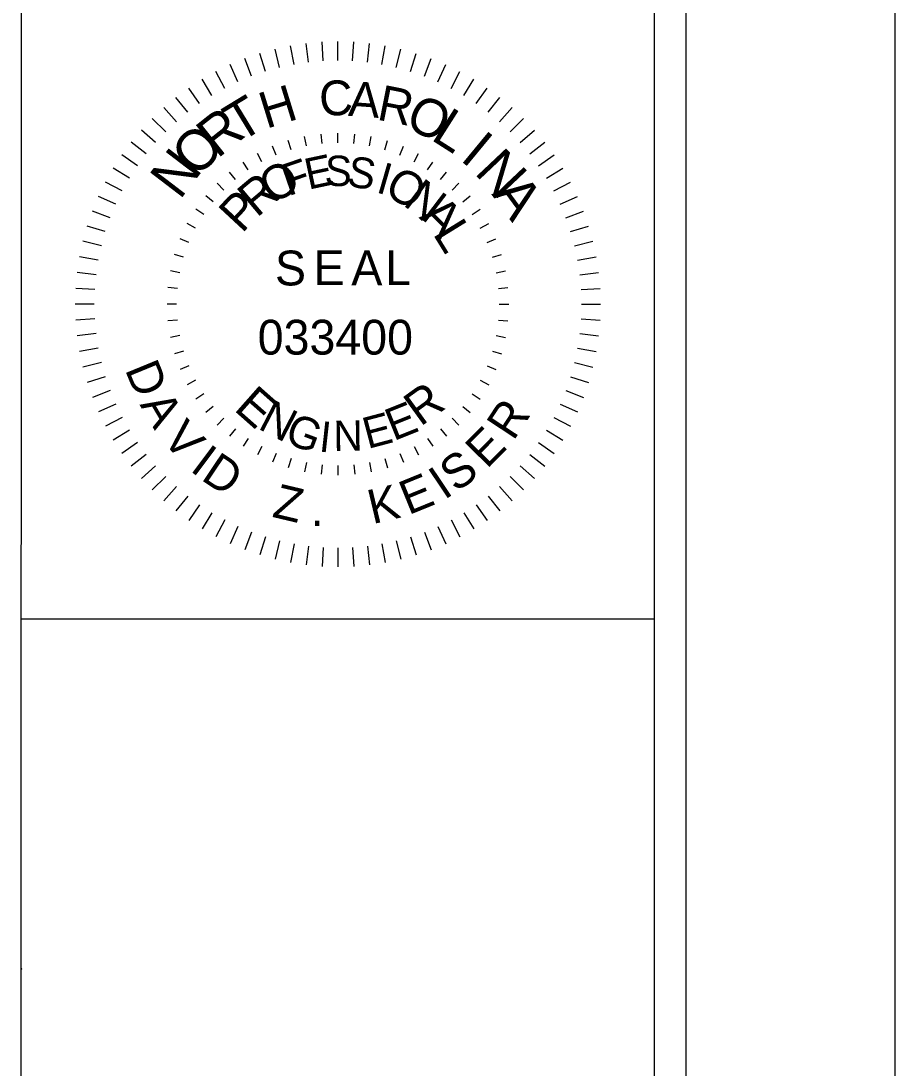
# Model space of a CAD drawing. Extents: x -2362 to 1945, y 0 to 1100.
# Drawn here: x 1561.9 to 1700, y 775.7 to 941 of the extents above; entities that cross this region are included whole.
import ezdxf

# ---------------------------------------------------------------- set-up
doc = ezdxf.new("R2010")
doc.units = 0
for name, color, linetype in [('Exist Utilities Telephone Test Hole SUE LOS A CELL', 7, 'Continuous'), ('Exist Utilities Water Test Hole SUE LOS A CELL', 7, 'Continuous'), ('Sheet PE Seal CELL', 7, 'Continuous'), ('Sheet_Symbology_CELL', 7, 'Continuous'), ('z - Construction', 7, 'Continuous')]:
    doc.layers.add(name, color=color, linetype=linetype)

msp = doc.modelspace()

# ---------------------------------------------------------------- linework, layer by layer
at = {"layer": 'Exist Utilities Telephone Test Hole SUE LOS A CELL'}
msp.add_line((1699.98, 0), (1699.98, 1100), dxfattribs=at)
at = {"layer": 'Exist Utilities Water Test Hole SUE LOS A CELL'}
msp.add_circle((1561.99, 791.38), 0.0603, dxfattribs=at)
at = {"layer": 'Sheet PE Seal CELL'}
msp.add_line((1661.97, 846.56), (1561.97, 846.56), dxfattribs=at)
at = {"layer": 'Sheet_Symbology_CELL'}
for p, q in [((1607.36, 934.51), (1607, 937.48)), ((1609.67, 934.72), (1609.49, 937.71)), ((1612, 934.79), (1612, 937.79)), ((1614.32, 934.72), (1614.5, 937.71)), ((1616.64, 934.51), (1617, 937.48)), ((1600.55, 933.04), (1599.66, 935.91)), ((1602.79, 933.67), (1602.07, 936.58)), ((1605.06, 934.16), (1604.52, 937.11)), ((1618.93, 934.16), (1619.48, 937.11)), ((1621.21, 933.67), (1621.92, 936.58)), ((1623.44, 933.04), (1624.34, 935.91)), ((1596.21, 931.4), (1594.98, 934.13)), ((1598.35, 932.29), (1597.29, 935.09)), ((1625.64, 932.29), (1626.71, 935.09)), ((1627.79, 931.4), (1629.02, 934.13)), ((1594.12, 930.38), (1592.72, 933.03)), ((1629.88, 930.38), (1631.27, 933.03)), ((1592.09, 929.24), (1590.54, 931.81)), ((1631.9, 929.24), (1633.45, 931.81)), ((1590.14, 927.98), (1588.44, 930.44)), ((1633.85, 927.98), (1635.56, 930.44)), ((1588.27, 926.6), (1586.42, 928.96)), ((1635.73, 926.6), (1637.58, 928.96)), ((1586.48, 925.11), (1584.49, 927.35)), ((1637.51, 925.11), (1639.5, 927.36)), ((1584.79, 923.52), (1582.67, 925.64)), ((1639.21, 923.52), (1641.32, 925.64)), ((1583.2, 921.82), (1580.95, 923.81)), ((1607.03, 921.31), (1606.73, 922.78)), ((1609.5, 921.67), (1609.35, 923.16)), ((1612, 921.8), (1612, 923.29)), ((1614.5, 921.67), (1614.64, 923.16)), ((1616.97, 921.31), (1617.26, 922.78)), ((1640.8, 921.82), (1643.04, 923.81)), ((1581.71, 920.04), (1579.35, 921.89)), ((1602.25, 919.85), (1601.67, 921.24)), ((1604.6, 920.7), (1604.16, 922.13)), ((1619.39, 920.7), (1619.83, 922.13)), ((1621.75, 919.85), (1622.33, 921.24)), ((1642.29, 920.04), (1644.65, 921.89)), ((1580.33, 918.17), (1577.87, 919.87)), ((1599.98, 918.79), (1599.28, 920.11)), ((1624.01, 918.79), (1624.72, 920.11)), ((1643.66, 918.17), (1646.13, 919.87)), ((1579.07, 916.22), (1576.5, 917.77)), ((1597.84, 917.5), (1597.01, 918.75)), ((1626.16, 917.5), (1626.99, 918.75)), ((1644.93, 916.22), (1647.49, 917.77)), ((1595.83, 916.01), (1594.88, 917.17)), ((1628.17, 916.01), (1629.12, 917.17)), ((1577.93, 914.19), (1575.27, 915.58)), ((1593.98, 914.33), (1592.92, 915.39)), ((1630.02, 914.33), (1631.08, 915.39)), ((1646.07, 914.19), (1648.72, 915.59)), ((1576.91, 912.1), (1574.18, 913.33)), ((1592.3, 912.48), (1591.14, 913.43)), ((1631.7, 912.48), (1632.86, 913.43)), ((1647.09, 912.1), (1649.82, 913.33)), ((1576.02, 909.95), (1573.22, 911.02)), ((1590.81, 910.47), (1589.56, 911.3)), ((1633.19, 910.47), (1634.44, 911.3)), ((1647.97, 909.95), (1650.78, 911.02)), ((1575.26, 907.76), (1572.4, 908.65)), ((1589.52, 908.32), (1588.2, 909.03)), ((1634.47, 908.32), (1635.8, 909.03)), ((1648.74, 907.76), (1651.59, 908.65)), ((1574.64, 905.52), (1571.73, 906.24)), ((1588.45, 906.06), (1587.07, 906.63)), ((1635.54, 906.06), (1636.93, 906.63)), ((1649.36, 905.52), (1652.27, 906.24)), ((1574.15, 903.25), (1571.2, 903.79)), ((1587.61, 903.71), (1586.17, 904.14)), ((1636.38, 903.71), (1637.82, 904.14)), ((1649.84, 903.25), (1652.8, 903.79)), ((1573.8, 900.95), (1570.82, 901.31)), ((1587, 901.28), (1585.53, 901.57)), ((1636.99, 901.28), (1638.46, 901.57)), ((1650.19, 900.95), (1653.17, 901.31)), ((1573.59, 898.63), (1570.6, 898.81)), ((1586.64, 898.81), (1585.14, 898.95)), ((1637.36, 898.81), (1638.85, 898.95)), ((1650.41, 898.63), (1653.4, 898.81)), ((1573.52, 896.31), (1570.52, 896.31)), ((1586.51, 896.31), (1585.01, 896.31)), ((1637.48, 896.31), (1638.98, 896.31)), ((1650.48, 896.31), (1653.47, 896.31)), ((1573.59, 893.99), (1570.6, 893.81)), ((1586.64, 893.81), (1585.14, 893.67)), ((1637.36, 893.81), (1638.85, 893.67)), ((1650.41, 893.99), (1653.4, 893.81)), ((1573.8, 891.67), (1570.82, 891.31)), ((1587, 891.34), (1585.53, 891.05)), ((1636.99, 891.34), (1638.46, 891.05)), ((1650.19, 891.67), (1653.17, 891.31)), ((1574.15, 889.37), (1571.2, 888.83)), ((1587.61, 888.91), (1586.17, 888.48)), ((1636.38, 888.91), (1637.82, 888.48)), ((1649.84, 889.37), (1652.79, 888.83)), ((1574.64, 887.1), (1571.73, 886.38)), ((1588.45, 886.56), (1587.07, 885.98)), ((1635.54, 886.56), (1636.93, 885.98)), ((1649.36, 887.1), (1652.27, 886.38)), ((1575.26, 884.86), (1572.4, 883.97)), ((1648.74, 884.86), (1651.59, 883.97)), ((1589.52, 884.3), (1588.2, 883.59)), ((1634.47, 884.3), (1635.8, 883.59)), ((1576.02, 882.66), (1573.22, 881.6)), ((1590.81, 882.15), (1589.56, 881.32)), ((1633.19, 882.15), (1634.44, 881.32)), ((1647.97, 882.66), (1650.78, 881.6)), ((1576.91, 880.52), (1574.18, 879.29)), ((1592.3, 880.14), (1591.14, 879.19)), ((1631.7, 880.14), (1632.86, 879.19)), ((1647.09, 880.52), (1649.82, 879.29)), ((1577.93, 878.43), (1575.27, 877.04)), ((1593.98, 878.29), (1592.92, 877.23)), ((1630.02, 878.29), (1631.08, 877.23)), ((1646.07, 878.43), (1648.72, 877.04)), ((1579.07, 876.4), (1576.5, 874.85)), ((1595.83, 876.61), (1594.88, 875.45)), ((1628.17, 876.61), (1629.12, 875.45)), ((1644.93, 876.4), (1647.49, 874.85)), ((1597.84, 875.12), (1597.01, 873.87)), ((1626.16, 875.12), (1626.99, 873.87)), ((1580.33, 874.45), (1577.87, 872.75)), ((1599.98, 873.83), (1599.28, 872.51)), ((1624.01, 873.83), (1624.72, 872.51)), ((1643.66, 874.45), (1646.13, 872.75)), ((1581.71, 872.58), (1579.35, 870.73)), ((1602.25, 872.76), (1601.67, 871.38)), ((1604.6, 871.92), (1604.16, 870.49)), ((1607.03, 871.32), (1606.73, 869.84)), ((1616.97, 871.31), (1617.26, 869.84)), ((1619.39, 871.92), (1619.83, 870.49)), ((1621.75, 872.76), (1622.33, 871.38)), ((1642.29, 872.58), (1644.65, 870.73)), ((1583.2, 870.8), (1580.95, 868.81)), ((1609.5, 870.95), (1609.35, 869.46)), ((1612, 870.83), (1612, 869.33)), ((1614.5, 870.95), (1614.64, 869.46)), ((1640.8, 870.8), (1643.04, 868.81)), ((1584.79, 869.1), (1582.67, 866.98)), ((1639.21, 869.1), (1641.32, 866.98)), ((1586.48, 867.51), (1584.49, 865.27)), ((1637.51, 867.51), (1639.5, 865.27)), ((1588.27, 866.02), (1586.42, 863.66)), ((1635.73, 866.02), (1637.58, 863.66)), ((1590.14, 864.64), (1588.44, 862.18)), ((1592.09, 863.38), (1590.54, 860.82)), ((1631.9, 863.38), (1633.45, 860.82)), ((1633.85, 864.64), (1635.56, 862.18)), ((1594.12, 862.24), (1592.72, 859.58)), ((1629.88, 862.24), (1631.27, 859.58)), ((1596.21, 861.22), (1594.98, 858.49)), ((1598.35, 860.33), (1597.29, 857.53)), ((1625.64, 860.33), (1626.71, 857.53)), ((1627.79, 861.22), (1629.02, 858.49)), ((1600.55, 859.57), (1599.66, 856.71)), ((1602.79, 858.95), (1602.07, 856.04)), ((1605.06, 858.46), (1604.52, 855.51)), ((1607.36, 858.11), (1607, 855.14)), ((1616.64, 858.11), (1617, 855.14)), ((1618.93, 858.46), (1619.48, 855.51)), ((1621.21, 858.95), (1621.92, 856.04)), ((1623.44, 859.57), (1624.34, 856.71)), ((1609.67, 857.9), (1609.49, 854.91)), ((1612, 857.83), (1612, 854.83)), ((1614.32, 857.9), (1614.5, 854.91))]:
    msp.add_line(p, q, dxfattribs=at)
at = {"layer": 'z - Construction'}
for p, q in [((1561.97, 39.96), (1562, 1059.93)), ((1662, 39.96), (1662, 1059.91)), ((1667, 39.99), (1667, 1059.91))]:
    msp.add_line(p, q, dxfattribs=at)

# ---------------------------------------------------------------- texts
at = {"layer": 'Sheet_Symbology_CELL'}
for s, height, rotation, p in [('H', 5.73, 17.1424, (1600.66, 923.98)), ('C', 5.5, 2.964, (1609.17, 925.99)), ('A', 5.51, 355.8747, (1613.53, 926.06)), ('R', 5.6, 348.7855, (1617.99, 925.48)), ('T', 6.13, 31.3209, (1596.48, 921.73)), ('O', 5.96, 334.607, (1622.35, 924.36)), ('R', 6.3, 38.4101, (1592.94, 919.2)), ('L', 6.16, 327.5178, (1626.5, 922.38)), ('O', 6.4, 45.4993, (1589.69, 916.1)), ('I', 6.32, 320.4286, (1631.13, 919.14)), ('N', 6.4, 52.5886, (1587.01, 912.65)), ('N', 6.41, 313.3394, (1633.4, 917.02)), ('F', 5.04, 18.9979, (1604.16, 913.33)), ('E', 4.9, 11.9657, (1607.32, 914.37)), ('S', 4.8, 357.9015, (1609.83, 915.04)), ('S', 4.86, 350.8694, (1613.25, 914.99)), ('O', 5.39, 33.0621, (1601.8, 911.92)), ('I', 4.98, 343.8373, (1617.85, 914.02)), ('O', 5.32, 329.773, (1619.07, 913.77)), ('R', 5.53, 40.0942, (1599.16, 909.87)), ('N', 5.48, 322.7409, (1622.1, 912.05)), ('A', 6.39, 306.2501, (1636.19, 913.68)), ('P', 5.6, 47.1264, (1596.83, 907.37)), ('A', 5.58, 315.7088, (1624.7, 909.96)), ('L', 5.51, 301.6445, (1626.9, 907.45)), ('S', 5.5, 0, (1602.05, 899.27)), ('E', 5.5, 0, (1608.15, 899.32)), ('A', 5.5, 0, (1614.11, 899.3)), ('L', 5.5, 0, (1619.43, 899.32)), ('033400', 5.497, 0, (1599.32, 888.35)), ('D', 5.4, 292.3254, (1578.31, 886.02)), ('E', 5.55, 318.5439, (1595.41, 879.65)), ('R', 5.45, 35.8972, (1625.02, 876.9)), ('A', 5.4, 300.5566, (1580.64, 880.44)), ('N', 5.25, 332.6082, (1599.18, 876.73)), ('E', 5.11, 21.833, (1620.79, 874.66)), ('R', 5.4, 56.6621, (1639.7, 874.6)), ('V', 5.4, 311.7772, (1584.07, 874.92)), ('G', 5.07, 339.6403, (1603.37, 874.51)), ('N', 4.8, 0.7366, (1611.3, 873.13)), ('E', 4.95, 14.8009, (1616.69, 873.43)), ('I', 4.83, 353.7045, (1608.88, 873.07)), ('E', 5.4, 45.3772, (1635.5, 870.19)), ('I', 5.4, 323.2372, (1588.48, 870.1)), ('S', 5.4, 36.7617, (1630.68, 866.49)), ('D', 5.4, 326.1338, (1590.2, 868.69)), ('E', 5.4, 22.1784, (1623.13, 862.97)), ('I', 5.4, 33.8651, (1628.78, 865.33)), ('Z', 5.4, 346.6654, (1601.46, 862.76)), ('K', 5.4, 13.3335, (1617.45, 861.56)), ('.', 5.4, 358.5162, (1607.7, 861.33))]:
    msp.add_text(s, height=height, rotation=rotation, dxfattribs=at).set_placement(p)

doc.saveas('drawing.dxf')
